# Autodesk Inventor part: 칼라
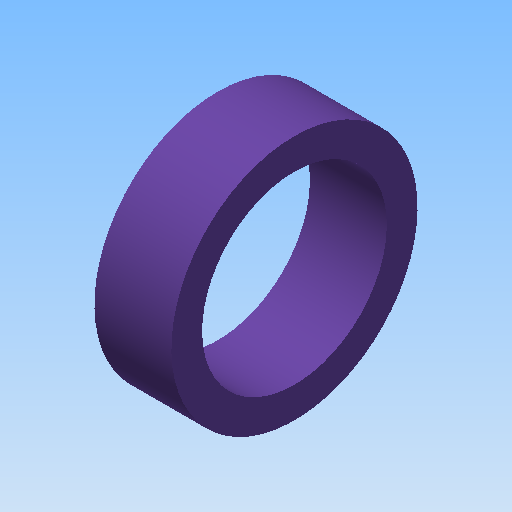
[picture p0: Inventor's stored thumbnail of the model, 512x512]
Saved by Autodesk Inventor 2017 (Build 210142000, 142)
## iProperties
Created: 2020-04
Part Number: 칼라
Material: 강철, 연강
Document SubType Name: Modeling
Designer: mduedu
Density: 1 g/cm^3
Appearance: 보라색
Author: mduedu
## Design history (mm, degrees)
sketch "스케치1"
  geometry: C1 r 8 at (0, 0); C2 r 6 at (0, 0); 1 further point
  constraints: 2 centre point, 2 coincident
  dimensions: "d0" = 16 diameter of C1; "d1" = 12 diameter of C2
extrude "돌출1" new body sketch "스케치1" distance "d2" = 5; taper "d3" = 0 deg
node "솔리드1"
